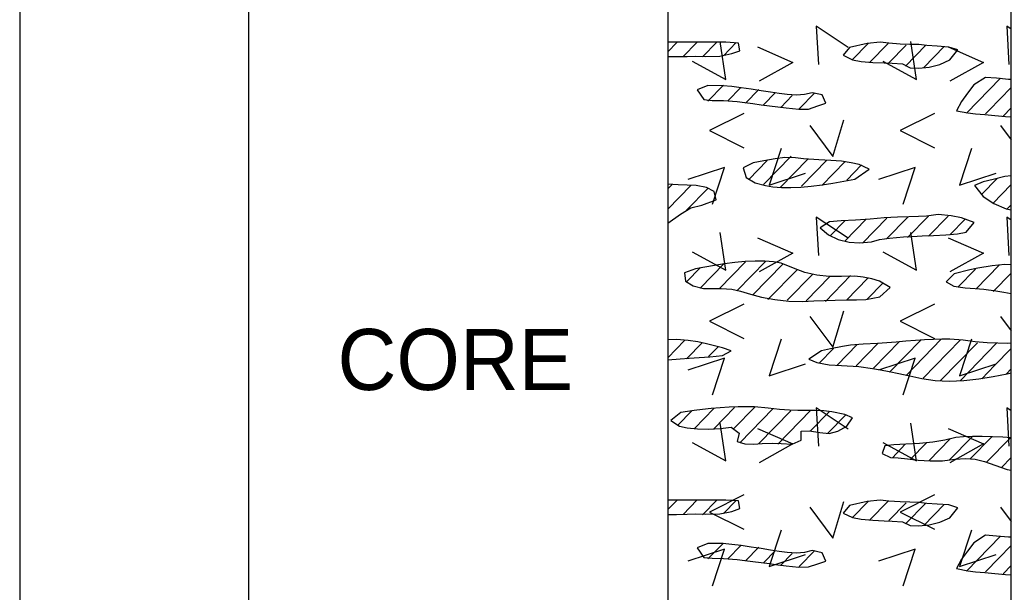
# Model space of a CAD drawing. Extents: x -0.01 to 0.83, y -0.63 to 1.27.
# Drawn here: x 0.725 to 0.8333, y -0.5615 to -0.499 of the extents above; entities that cross this region are included whole.
import ezdxf

# ---------------------------------------------------------------- set-up
doc = ezdxf.new("R2010")
doc.units = 0

msp = doc.modelspace()

# ---------------------------------------------------------------- linework, layer by layer
for points in [[(0.725, 1.22083), (0.725, -0.62183)], [(0.75, 1.22083), (0.75, -0.62183)], [(0.75, 1.22083), (0.75, -0.62183)], [(0.79583, 1.22083), (0.79583, -0.62183)], [(0.725, 1.20833), (0.725, -0.62183)], [(0.83333, -0.62183), (0.83333, 1.13843)], [(0.81551, -0.50206), (0.81201, -0.49974), (0.81226, -0.50393)], [(0.83333, -0.50006), (0.83284, -0.49974), (0.83309, -0.50393)], [(0.79583, -0.50252), (0.79681, -0.50152)], [(0.79898, -0.5015), (0.79747, -0.50305)], [(0.79847, -0.50354), (0.80215, -0.50554), (0.80153, -0.50141)], [(0.80116, -0.50148), (0.79959, -0.50309)], [(0.80328, -0.50152), (0.80188, -0.50295)], [(0.8193, -0.50354), (0.82299, -0.50554), (0.82236, -0.50141)], [(0.80562, -0.50199), (0.80946, -0.50368), (0.80581, -0.50574)], [(0.8177, -0.50162), (0.81596, -0.50341)], [(0.81988, -0.50161), (0.81785, -0.50368)], [(0.82185, -0.50179), (0.81997, -0.50372)], [(0.824, -0.50181), (0.82178, -0.50409)], [(0.82601, -0.50196), (0.82378, -0.50424)], [(0.82645, -0.50199), (0.83029, -0.50368), (0.82664, -0.50574)], [(0.83217, -0.50541), (0.82844, -0.50923)], [(0.80188, -0.50618), (0.8002, -0.50791)], [(0.8038, -0.50643), (0.80237, -0.50789)], [(0.80575, -0.50664), (0.80429, -0.50814)], [(0.80758, -0.50698), (0.80627, -0.50832)], [(0.83333, -0.50643), (0.83093, -0.50889), (0.83052, -0.50931)], [(0.80941, -0.50731), (0.80816, -0.5086)], [(0.81188, -0.507), (0.81016, -0.50875)], [(0.83333, -0.50864), (0.83245, -0.50954)], [(0.80412, -0.50925), (0.80038, -0.51113), (0.80412, -0.513)], [(0.81134, -0.51059), (0.81384, -0.51397), (0.81503, -0.50997)], [(0.82496, -0.50925), (0.82121, -0.51113), (0.82496, -0.513)], [(0.83217, -0.51059), (0.83333, -0.51215)], [(0.80818, -0.51308), (0.80687, -0.51708), (0.81087, -0.51577)], [(0.82901, -0.51308), (0.8277, -0.51708), (0.8317, -0.51577)], [(0.80465, -0.51646), (0.80667, -0.51439)], [(0.80626, -0.51703), (0.80928, -0.51393)], [(0.80809, -0.51736), (0.81111, -0.51426)], [(0.81041, -0.5172), (0.81318, -0.51436)], [(0.81264, -0.51712), (0.81518, -0.51452)], [(0.80069, -0.51916), (0.802, -0.51516), (0.798, -0.51648)], [(0.81536, -0.51655), (0.81699, -0.51488)], [(0.82152, -0.51916), (0.82284, -0.51516), (0.81884, -0.51648)], [(0.8301, -0.51812), (0.83184, -0.51634)], [(0.7963, -0.51701), (0.79583, -0.51749)], [(0.79834, -0.51713), (0.79583, -0.5197)], [(0.79786, -0.51983), (0.80023, -0.51741)], [(0.83131, -0.5191), (0.83333, -0.51702)], [(0.83285, -0.51972), (0.83333, -0.51923)], [(0.81551, -0.52289), (0.81201, -0.52058), (0.81226, -0.52476)], [(0.81519, -0.52094), (0.81354, -0.52263)], [(0.81514, -0.5232), (0.81748, -0.52081)], [(0.81709, -0.52342), (0.81974, -0.5207)], [(0.8197, -0.52296), (0.82203, -0.52057)], [(0.82202, -0.5228), (0.8243, -0.52046)], [(0.82431, -0.52266), (0.82644, -0.52047)], [(0.82663, -0.5225), (0.82834, -0.52075)], [(0.83333, -0.5209), (0.83284, -0.52058), (0.83309, -0.52476)], [(0.79847, -0.52437), (0.80215, -0.52637), (0.80153, -0.52225)], [(0.80562, -0.52283), (0.80946, -0.52451), (0.80581, -0.52657)], [(0.8193, -0.52437), (0.82299, -0.52637), (0.82236, -0.52225)], [(0.82645, -0.52283), (0.83029, -0.52451), (0.82664, -0.52657)], [(0.80653, -0.52539), (0.8034, -0.5286)], [(0.79938, -0.52608), (0.79786, -0.52763)], [(0.79933, -0.52834), (0.80195, -0.52566)], [(0.80142, -0.52842), (0.8043, -0.52546)], [(0.80506, -0.52911), (0.8084, -0.52569)], [(0.80997, -0.52629), (0.80675, -0.52959)], [(0.82751, -0.52824), (0.82945, -0.52625)], [(0.83203, -0.52582), (0.82949, -0.52842)], [(0.81164, -0.5268), (0.80884, -0.52966)], [(0.81353, -0.52707), (0.81094, -0.52973)], [(0.81303, -0.52979), (0.81579, -0.52697)], [(0.81534, -0.52964), (0.81768, -0.52724)], [(0.83138, -0.5287), (0.83333, -0.5267)], [(0.8176, -0.52953), (0.81934, -0.52775)], [(0.83333, -0.52891), (0.83333, -0.52891)], [(0.80412, -0.53008), (0.80038, -0.53196), (0.80412, -0.53383)], [(0.81134, -0.53143), (0.81384, -0.5348), (0.81503, -0.5308)], [(0.82496, -0.53008), (0.82121, -0.53196), (0.82496, -0.53383)], [(0.83217, -0.53143), (0.83333, -0.53299)], [(0.79765, -0.53406), (0.79583, -0.53593)], [(0.80818, -0.53392), (0.80687, -0.53792), (0.81087, -0.5366)], [(0.82004, -0.5375), (0.82346, -0.534)], [(0.82569, -0.53392), (0.82184, -0.53787)], [(0.82775, -0.53402), (0.8237, -0.53817)], [(0.82901, -0.53392), (0.8277, -0.53792), (0.8317, -0.5366)], [(0.7996, -0.53428), (0.79786, -0.53606)], [(0.8013, -0.53476), (0.80027, -0.53581)], [(0.81392, -0.53491), (0.81235, -0.53652)], [(0.8143, -0.53674), (0.8165, -0.53449)], [(0.8164, -0.53681), (0.81879, -0.53435)], [(0.81829, -0.53708), (0.82114, -0.53416)], [(0.82964, -0.5343), (0.82557, -0.53847)], [(0.83173, -0.53436), (0.82774, -0.53845)], [(0.83333, -0.53494), (0.83152, -0.5368), (0.83012, -0.53823)], [(0.80069, -0.54), (0.802, -0.536), (0.798, -0.53731)], [(0.82152, -0.54), (0.82284, -0.536), (0.81884, -0.53731)], [(0.83281, -0.53769), (0.83333, -0.53715)], [(0.79871, -0.54366), (0.80085, -0.54147)], [(0.80083, -0.54371), (0.80311, -0.54137)], [(0.80534, -0.54129), (0.80299, -0.54371)], [(0.80367, -0.54522), (0.80732, -0.54148)], [(0.81551, -0.54372), (0.81201, -0.54141), (0.81226, -0.5456)], [(0.83333, -0.54173), (0.83284, -0.54141), (0.83309, -0.5456)], [(0.79844, -0.54172), (0.79691, -0.54329)], [(0.80571, -0.54534), (0.80924, -0.54172)], [(0.81142, -0.5417), (0.80785, -0.54536)], [(0.81141, -0.54393), (0.81348, -0.5418)], [(0.81528, -0.54217), (0.81331, -0.54419)], [(0.79847, -0.5452), (0.80215, -0.5472), (0.80153, -0.54308)], [(0.80562, -0.54366), (0.80946, -0.54534), (0.80581, -0.5474)], [(0.8193, -0.5452), (0.82299, -0.5472), (0.82236, -0.54308)], [(0.82645, -0.54366), (0.83029, -0.54534), (0.82664, -0.5474)], [(0.82433, -0.54719), (0.82666, -0.5448)], [(0.82909, -0.54452), (0.82656, -0.54711)], [(0.82885, -0.54698), (0.83122, -0.54456)], [(0.83325, -0.54469), (0.83065, -0.54735)], [(0.82035, -0.54685), (0.82176, -0.54539)], [(0.82233, -0.54702), (0.82408, -0.54524)], [(0.83333, -0.54682), (0.83227, -0.54791)], [(0.80412, -0.55092), (0.80038, -0.55279), (0.80412, -0.55467)], [(0.82496, -0.55092), (0.82121, -0.55279), (0.82496, -0.55467)], [(0.79583, -0.55252), (0.79681, -0.55152)], [(0.79898, -0.5515), (0.79747, -0.55305)], [(0.80116, -0.55148), (0.79959, -0.55309)], [(0.80328, -0.55152), (0.80188, -0.55295)], [(0.81134, -0.55226), (0.81384, -0.55563), (0.81503, -0.55163)], [(0.8177, -0.55162), (0.81596, -0.55341)], [(0.81988, -0.55161), (0.81785, -0.55368)], [(0.82185, -0.55179), (0.81997, -0.55372)], [(0.824, -0.55181), (0.82178, -0.55409)], [(0.82601, -0.55196), (0.82378, -0.55424)], [(0.83217, -0.55226), (0.83333, -0.55382)], [(0.80818, -0.55475), (0.80687, -0.55875), (0.81087, -0.55744)], [(0.82901, -0.55475), (0.8277, -0.55875), (0.8317, -0.55744)], [(0.83217, -0.55541), (0.82844, -0.55923)], [(0.80069, -0.56083), (0.802, -0.55683), (0.798, -0.55814)], [(0.80188, -0.55618), (0.8002, -0.55791)], [(0.8038, -0.55643), (0.80237, -0.55789)], [(0.80575, -0.55664), (0.80429, -0.55813)], [(0.82152, -0.56083), (0.82284, -0.55683), (0.81884, -0.55814)], [(0.83333, -0.55643), (0.83197, -0.55783), (0.83052, -0.55931)], [(0.80758, -0.55698), (0.80627, -0.55832)], [(0.80941, -0.55731), (0.80816, -0.5586)], [(0.81188, -0.557), (0.81016, -0.55875)], [(0.83333, -0.55864), (0.83245, -0.55954)]]:
    msp.add_lwpolyline(points)
for points in [[(0.79583, -0.50304), (0.79676, -0.50305), (0.79792, -0.50303), (0.79882, -0.50299), (0.79992, -0.50303), (0.80151, -0.50299), (0.80282, -0.50273), (0.80367, -0.50241), (0.80354, -0.50157), (0.80216, -0.50149), (0.79583, -0.50149)], [(0.81822, -0.50368), (0.81944, -0.50374), (0.82033, -0.50378), (0.82145, -0.50385), (0.82229, -0.50426), (0.82324, -0.50431), (0.82438, -0.5042), (0.82555, -0.50391), (0.82662, -0.50341), (0.82749, -0.50231), (0.82651, -0.50201), (0.82524, -0.50191), (0.82413, -0.50184), (0.82324, -0.50174), (0.82226, -0.50172), (0.82121, -0.50169), (0.81995, -0.5016), (0.81902, -0.50149), (0.81761, -0.50163), (0.81566, -0.50207), (0.81496, -0.50291), (0.81598, -0.5034), (0.81695, -0.50357)], [(0.83305, -0.50554), (0.83171, -0.50542), (0.83054, -0.50532), (0.82925, -0.50614), (0.82857, -0.50706), (0.82792, -0.50794), (0.82735, -0.50897), (0.82858, -0.5092), (0.82945, -0.5093), (0.83045, -0.50939), (0.83155, -0.50949), (0.83272, -0.50959), (0.83333, -0.50964), (0.83333, -0.50554)], [(0.80066, -0.50784), (0.80188, -0.50785), (0.80339, -0.50797), (0.80423, -0.50807), (0.8051, -0.50818), (0.806, -0.5083), (0.80692, -0.50842), (0.80784, -0.50854), (0.80875, -0.50865), (0.81014, -0.50879), (0.81119, -0.50878), (0.81222, -0.50843), (0.81308, -0.50815), (0.81267, -0.50724), (0.8116, -0.507), (0.81075, -0.5072), (0.80989, -0.50728), (0.80885, -0.5072), (0.80799, -0.50709), (0.80703, -0.50694), (0.806, -0.50678), (0.80492, -0.50661), (0.80384, -0.50645), (0.8028, -0.50632), (0.80182, -0.50623), (0.8002, -0.50622), (0.79901, -0.50669), (0.79974, -0.50774)], [(0.81233, -0.51434), (0.81063, -0.51423), (0.80977, -0.51409), (0.8086, -0.51408), (0.80755, -0.51423), (0.80632, -0.51443), (0.80513, -0.51467), (0.80403, -0.51519), (0.80436, -0.51625), (0.80536, -0.51682), (0.80647, -0.51712), (0.8073, -0.51727), (0.80824, -0.51734), (0.80926, -0.51735), (0.81035, -0.5173), (0.81149, -0.5172), (0.81267, -0.51705), (0.81386, -0.51687), (0.81506, -0.51666), (0.81625, -0.51642), (0.81783, -0.51534), (0.81673, -0.51484), (0.81585, -0.51464), (0.8148, -0.51448), (0.81361, -0.51438)], [(0.83265, -0.51616), (0.83136, -0.51647), (0.83028, -0.51674), (0.82934, -0.51713), (0.83026, -0.51833), (0.83142, -0.5191), (0.83279, -0.51968), (0.83333, -0.51977), (0.83333, -0.51607)], [(0.79583, -0.52125), (0.79719, -0.52026), (0.79831, -0.51956), (0.79951, -0.51929), (0.80111, -0.51869), (0.80086, -0.5178), (0.80002, -0.51733), (0.79889, -0.51713), (0.79791, -0.5171), (0.79694, -0.51705), (0.79583, -0.51697)], [(0.82537, -0.52031), (0.82408, -0.52046), (0.82319, -0.52052), (0.82214, -0.52054), (0.82091, -0.52058), (0.81947, -0.52067), (0.81792, -0.52079), (0.81632, -0.52091), (0.81475, -0.521), (0.81348, -0.5211), (0.81247, -0.52174), (0.81337, -0.5225), (0.81444, -0.52301), (0.81561, -0.5233), (0.81675, -0.5234), (0.81807, -0.52329), (0.81896, -0.52301), (0.82003, -0.52287), (0.82157, -0.52275), (0.82253, -0.52269), (0.82362, -0.52263), (0.82483, -0.52257), (0.82618, -0.5225), (0.82745, -0.5224), (0.82842, -0.52222), (0.82927, -0.52117), (0.82791, -0.52065), (0.82679, -0.52045)], [(0.79885, -0.52622), (0.79763, -0.52668), (0.79773, -0.52758), (0.79859, -0.5281), (0.7997, -0.52839), (0.80074, -0.52838), (0.80165, -0.52837), (0.80281, -0.52845), (0.80377, -0.52866), (0.80486, -0.52901), (0.80606, -0.52931), (0.80751, -0.52958), (0.80905, -0.52977), (0.81052, -0.5298), (0.81177, -0.52974), (0.81289, -0.5297), (0.81408, -0.52966), (0.81553, -0.52962), (0.81642, -0.5296), (0.81745, -0.52957), (0.81897, -0.52929), (0.82011, -0.52826), (0.81896, -0.52759), (0.8181, -0.52732), (0.81717, -0.52712), (0.81626, -0.52702), (0.81479, -0.52708), (0.81343, -0.52708), (0.8121, -0.52693), (0.8108, -0.52662), (0.80953, -0.52616), (0.8082, -0.52561), (0.80736, -0.52545), (0.8064, -0.52538), (0.80536, -0.52538), (0.80427, -0.52544), (0.80314, -0.52555), (0.80201, -0.52569), (0.8009, -0.52586), (0.79984, -0.52604)], [(0.83263, -0.52577), (0.83126, -0.52591), (0.82969, -0.52617), (0.82883, -0.52635), (0.82712, -0.52676), (0.82623, -0.52763), (0.82708, -0.52812), (0.82831, -0.52831), (0.82941, -0.52837), (0.83033, -0.52846), (0.83165, -0.52864), (0.83253, -0.52879), (0.83333, -0.52893), (0.83333, -0.52578)], [(0.79583, -0.53618), (0.79715, -0.53606), (0.79814, -0.53599), (0.79922, -0.53591), (0.80039, -0.53583), (0.80179, -0.53571), (0.80275, -0.53519), (0.80179, -0.53485), (0.80091, -0.53464), (0.80003, -0.53442), (0.79909, -0.53421), (0.79803, -0.53404), (0.79677, -0.53395), (0.79583, -0.53397)], [(0.82816, -0.53842), (0.82978, -0.53825), (0.83137, -0.538), (0.8329, -0.53769), (0.83333, -0.53759), (0.83333, -0.53435), (0.83295, -0.53438), (0.83188, -0.53436), (0.83071, -0.5343), (0.82938, -0.5342), (0.82807, -0.53403), (0.82662, -0.53391), (0.82576, -0.53391), (0.82484, -0.53394), (0.82387, -0.53399), (0.82286, -0.53406), (0.82182, -0.53414), (0.82077, -0.53422), (0.81973, -0.5343), (0.81872, -0.53438), (0.81715, -0.53447), (0.81579, -0.53457), (0.81491, -0.5347), (0.81357, -0.53497), (0.8126, -0.53519), (0.81121, -0.53611), (0.8121, -0.53647), (0.81345, -0.53671), (0.81479, -0.5368), (0.81668, -0.53691), (0.81818, -0.53711), (0.81905, -0.53725), (0.82, -0.53743), (0.82107, -0.53765), (0.82225, -0.5379), (0.82357, -0.53819), (0.82501, -0.53841), (0.82656, -0.53848)], [(0.79708, -0.5434), (0.79794, -0.54358), (0.79904, -0.54369), (0.80028, -0.54373), (0.80156, -0.54367), (0.80274, -0.54352), (0.80361, -0.54418), (0.80338, -0.54508), (0.80422, -0.54535), (0.80517, -0.54537), (0.80613, -0.54531), (0.8072, -0.54528), (0.80818, -0.54531), (0.80939, -0.54539), (0.81037, -0.54492), (0.81038, -0.54397), (0.8113, -0.54391), (0.81244, -0.5441), (0.81346, -0.5442), (0.81438, -0.54395), (0.81539, -0.54341), (0.81601, -0.54249), (0.81517, -0.54212), (0.81374, -0.54184), (0.81285, -0.54175), (0.81187, -0.54169), (0.81, -0.54169), (0.8091, -0.54167), (0.808, -0.5416), (0.80678, -0.54144), (0.8053, -0.54131), (0.80443, -0.5413), (0.80349, -0.54131), (0.80251, -0.54135), (0.80152, -0.54142), (0.80054, -0.54149), (0.79959, -0.54159), (0.7987, -0.54168), (0.79722, -0.54191), (0.79614, -0.54279)], [(0.83241, -0.54462), (0.83129, -0.54456), (0.83017, -0.54452), (0.8291, -0.54452), (0.82811, -0.54456), (0.82728, -0.54465), (0.82608, -0.54495), (0.82476, -0.54517), (0.8233, -0.54531), (0.82183, -0.54539), (0.82051, -0.54545), (0.81951, -0.54555), (0.81922, -0.54641), (0.82013, -0.54683), (0.82097, -0.54688), (0.822, -0.54698), (0.82318, -0.54711), (0.82448, -0.5472), (0.82584, -0.54718), (0.82719, -0.54701), (0.82836, -0.54695), (0.8294, -0.54703), (0.83043, -0.54726), (0.83156, -0.54765), (0.83291, -0.54814), (0.83333, -0.54822), (0.83333, -0.5447)], [(0.79583, -0.55304), (0.79676, -0.55305), (0.79792, -0.55303), (0.79882, -0.55299), (0.79992, -0.55303), (0.80151, -0.55299), (0.80282, -0.55273), (0.80367, -0.55241), (0.80354, -0.55157), (0.80216, -0.55149), (0.79583, -0.55149)], [(0.81822, -0.55368), (0.81944, -0.55374), (0.82033, -0.55378), (0.82145, -0.55385), (0.82229, -0.55426), (0.82324, -0.55431), (0.82438, -0.5542), (0.82555, -0.55391), (0.82662, -0.55341), (0.82749, -0.55231), (0.82651, -0.55201), (0.82524, -0.55191), (0.82413, -0.55184), (0.82324, -0.55174), (0.82226, -0.55172), (0.82121, -0.55169), (0.81995, -0.5516), (0.81902, -0.55149), (0.81761, -0.55163), (0.81566, -0.55207), (0.81496, -0.55291), (0.81598, -0.5534), (0.81695, -0.55357)], [(0.83305, -0.55554), (0.83171, -0.55542), (0.83054, -0.55532), (0.82925, -0.55614), (0.82857, -0.55706), (0.82792, -0.55794), (0.82735, -0.55897), (0.82858, -0.5592), (0.82945, -0.5593), (0.83045, -0.55939), (0.83155, -0.55949), (0.83272, -0.55959), (0.83333, -0.55964), (0.83333, -0.55554)], [(0.80066, -0.55784), (0.80188, -0.55785), (0.80339, -0.55797), (0.80423, -0.55807), (0.8051, -0.55818), (0.806, -0.5583), (0.80692, -0.55842), (0.80784, -0.55854), (0.80875, -0.55865), (0.81014, -0.55879), (0.81119, -0.55878), (0.81222, -0.55843), (0.81308, -0.55815), (0.81267, -0.55724), (0.8116, -0.557), (0.81075, -0.5572), (0.80989, -0.55728), (0.80885, -0.5572), (0.80799, -0.55709), (0.80703, -0.55694), (0.806, -0.55678), (0.80492, -0.55661), (0.80384, -0.55645), (0.8028, -0.55632), (0.80182, -0.55623), (0.8002, -0.55622), (0.79901, -0.55669), (0.79974, -0.55774)]]:
    msp.add_lwpolyline(points, close=True)

# ---------------------------------------------------------------- texts
msp.add_text('CORE', height=0.006667).set_placement((0.75971, -0.53946))

doc.saveas('drawing.dxf')
